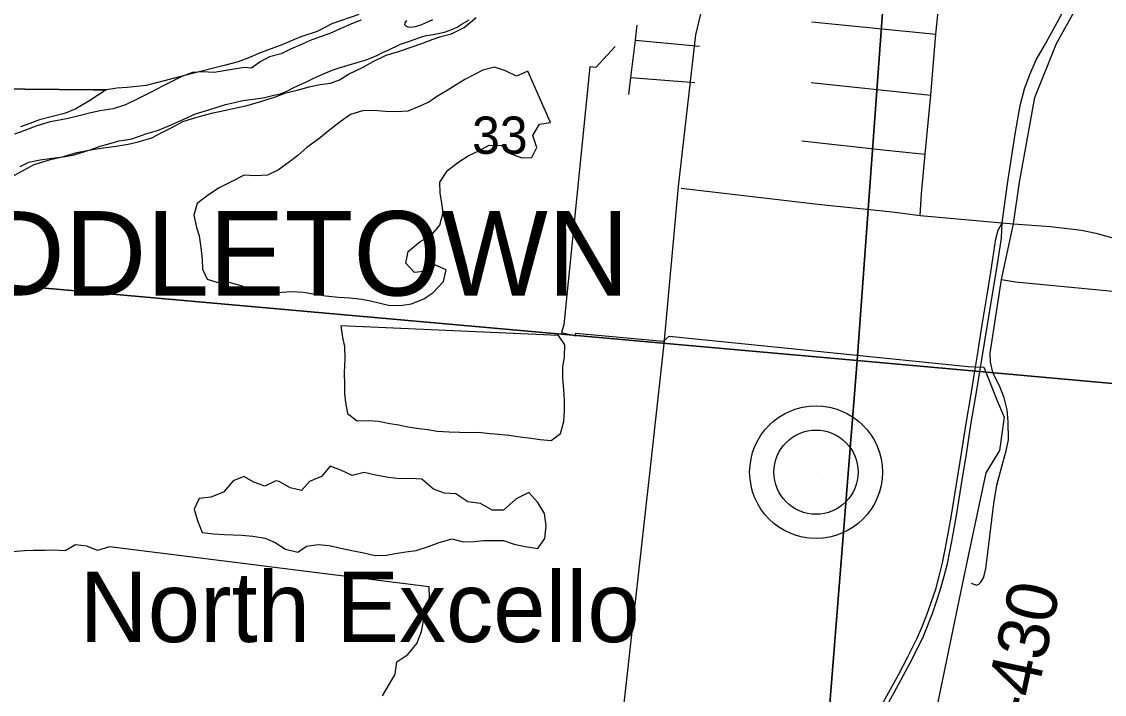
# Model space of a CAD drawing. Extents: x 0 to 34, y 0 to 22.
# Drawn here: x 4.533 to 5.747, y 15.439 to 16.193 of the extents above; entities that cross this region are included whole.
import ezdxf

# ---------------------------------------------------------------- set-up
doc = ezdxf.new("R2010")
doc.units = 0
for name, color, linetype in [('GM_X_City_Street', 7, 'Continuous'), ('GM_X_Corporation', 7, 'Continuous'), ('GM_X_Corporation_Text', 7, 'Continuous'), ('GM_X_County_Road', 7, 'Continuous'), ('GM_X_Major_River', 7, 'Continuous'), ('GM_X_Minor_Lake', 7, 'Continuous'), ('GM_X_Rail_Line', 7, 'Continuous'), ('GM_X_Section_Text', 7, 'Continuous'), ('GM_X_State_Route', 7, 'Continuous'), ('GM_X_Township_Road_Text', 7, 'Continuous'), ('GM_X_Unincorporated', 7, 'Continuous'), ('GM_X_Unincorporated_Location', 7, 'Continuous'), ('GM_X_Unincorporated_Text', 7, 'Continuous')]:
    doc.layers.add(name, color=color, linetype=linetype)

msp = doc.modelspace()

# ---------------------------------------------------------------- linework, layer by layer
at = {"layer": 'GM_X_City_Street'}
for p, q in [((5.4189, 16.1929), (5.5578, 16.1793)), ((5.2208, 16.1726), (5.2929, 16.1656)), ((5.2157, 16.1306), (5.2876, 16.1251)), ((5.4181, 16.1248), (5.5521, 16.1109))]:
    msp.add_line(p, q, dxfattribs=at)
for points in [[(5.5402, 15.9759), (5.5418, 16.0002), (5.546, 16.0446), (5.5521, 16.1109), (5.5578, 16.1793), (5.5645, 16.2444), (5.5717, 16.3105), (5.5762, 16.3524), (5.5785, 16.3733)], [(5.5973, 15.5632), (5.6032, 15.5612), (5.606, 15.5621), (5.6079, 15.5641), (5.6112, 15.5693), (5.6137, 15.5793), (5.623, 15.6529), (5.6262, 15.6733), (5.633, 15.6984), (5.6367, 15.7118), (5.6391, 15.7242), (5.6388, 15.7447), (5.6378, 15.7578), (5.6345, 15.7712), (5.6298, 15.7827), (5.6217, 15.7997), (5.6191, 15.8114), (5.6187, 15.8214), (5.6313, 15.904), (5.6449, 15.9664), (5.6515, 16.0131), (5.6577, 16.0459), (5.6687, 16.1082), (5.6931, 16.1687), (5.7153, 16.2082)], [(5.2134, 16.1115), (5.2157, 16.1306), (5.2208, 16.1726), (5.2228, 16.1891)], [(5.4076, 16.0595), (5.5022, 16.0491), (5.546, 16.0446)], [(5.6313, 15.904), (5.647, 15.9012), (5.7952, 15.887)]]:
    msp.add_lwpolyline(points, dxfattribs=at)
at = {"layer": 'GM_X_Corporation'}
for points in [[(5.5455, 16.8552), (5.4696, 15.8133), (4.4791, 15.9012)], [(4.9106, 16.2014), (4.8804, 16.1907), (4.864, 16.1823), (4.8456, 16.1763), (4.8242, 16.1673), (4.7994, 16.158), (4.788, 16.1529), (4.7754, 16.1483), (4.7613, 16.1444), (4.7197, 16.1339), (4.6721, 16.1217), (4.6509, 16.1195), (4.6395, 16.1186), (4.6326, 16.1176), (4.6273, 16.1166), (4.6133, 16.1169), (4.1502, 16.1212)], [(4.5308, 16.0308), (4.5407, 16.0355), (4.5533, 16.0383), (4.5643, 16.0396), (4.573, 16.0409), (4.5814, 16.0418), (4.5913, 16.0439), (4.6104, 16.0499), (4.6207, 16.0535), (4.6329, 16.057), (4.6416, 16.0595), (4.6473, 16.0601), (4.6561, 16.0618), (4.6637, 16.0643), (4.6717, 16.0672), (4.6851, 16.071), (4.6977, 16.0764), (4.7145, 16.084), (4.7275, 16.0898), (4.7424, 16.0944), (4.7611, 16.1001), (4.7713, 16.1025), (4.7805, 16.1046), (4.8036, 16.1079), (4.8155, 16.1107), (4.8227, 16.1124), (4.8307, 16.1156), (4.8384, 16.1196), (4.8514, 16.1254), (4.8617, 16.1305), (4.8736, 16.1359), (4.882, 16.1392), (4.8888, 16.1413), (4.9087, 16.1473), (4.9178, 16.1501), (4.93, 16.1548), (4.9381, 16.1588), (4.943, 16.1609), (4.9576, 16.1678), (4.9687, 16.1717), (4.9809, 16.176), (4.9866, 16.1778), (4.9942, 16.1788), (5.0067, 16.1815), (5.0151, 16.1844), (5.0209, 16.1869), (5.0266, 16.1906), (5.0343, 16.1953)], [(4.9934, 16.1951), (4.9808, 16.1897), (4.9739, 16.1875), (4.9686, 16.1865), (4.9659, 16.187), (4.9637, 16.1881), (4.9622, 16.1897), (4.9626, 16.192), (4.9646, 16.1946)], [(5.1983, 16.1652), (5.1765, 16.1419), (5.1697, 16.1427), (5.1405, 15.853), (5.1381, 15.8447), (5.1538, 15.8409), (5.1541, 15.8438), (5.2522, 15.835), (5.2587, 15.8404), (5.4471, 15.8212), (5.594, 15.8064), (5.6117, 15.8058), (5.6271, 15.7673), (5.6343, 15.7496), (5.6292, 15.712), (5.6139, 15.6872), (5.5936, 15.592), (5.5853, 15.5528), (5.5629, 15.4444), (5.5342, 15.3055)], [(4.1502, 16.1212), (4.6133, 16.1169), (4.6273, 16.1166), (4.6081, 16.1041), (4.5935, 16.0954), (4.5817, 16.0907), (4.5527, 16.083), (4.5417, 16.0791), (4.5314, 16.0751)]]:
    msp.add_lwpolyline(points, dxfattribs=at)
for points in [[(5.5455, 16.8552), (6.5907, 16.7563), (6.5598, 16.3771), (6.5104, 15.9318), (6.4956, 15.7207), (5.4696, 15.8133)], [(4.4791, 15.9012), (5.4696, 15.8133), (5.3881, 14.7897), (4.6238, 14.8425), (4.6032, 14.8565), (4.5856, 14.8637), (4.5735, 14.8663), (4.5679, 14.8668), (4.5637, 14.865), (4.5556, 14.8606), (4.5464, 14.8574), (4.5354, 14.8542), (4.5274, 14.851), (4.4054, 15.0286)], [(5.4696, 15.8133), (6.4956, 15.7207), (6.423, 14.72), (5.3881, 14.7897)]]:
    msp.add_lwpolyline(points, close=True, dxfattribs=at)
at = {"layer": 'GM_X_County_Road'}
for points in [[(5.2723, 16.0064), (5.429, 15.9882), (5.451, 15.9859)], [(5.451, 15.9859), (5.4731, 15.9837), (5.5054, 15.9802), (5.5203, 15.9784)], [(5.5203, 15.9784), (5.5402, 15.9759), (5.632, 15.9677)], [(5.632, 15.9677), (5.6449, 15.9664), (5.6862, 15.9633), (5.7212, 15.9592), (5.7372, 15.9561), (5.7521, 15.9519), (5.7668, 15.9473), (5.7841, 15.9435), (5.802, 15.9412), (5.8282, 15.9389), (5.9421, 15.9278), (6.0649, 15.9174), (6.1114, 15.9127), (6.1845, 15.9048), (6.2738, 15.8961), (6.3586, 15.8898), (6.3752, 15.8883), (6.4414, 15.8823), (6.496, 15.8771), (6.518, 15.8755)]]:
    msp.add_lwpolyline(points, dxfattribs=at)
at = {"layer": 'GM_X_Major_River'}
for points in [[(4.5203, 16.0188), (4.5341, 16.0264), (4.5468, 16.0329), (4.5648, 16.0385), (4.5794, 16.0419), (4.5943, 16.0465), (4.6122, 16.0498), (4.6244, 16.0517), (4.6386, 16.0536), (4.6519, 16.0559), (4.6634, 16.0583), (4.6787, 16.0628), (4.6899, 16.0689), (4.7026, 16.0754), (4.7134, 16.0812), (4.7268, 16.0854), (4.7371, 16.0882), (4.7474, 16.0909), (4.7596, 16.0936), (4.7696, 16.0957), (4.7856, 16.099), (4.7994, 16.1032), (4.8174, 16.1088), (4.8278, 16.1131), (4.8415, 16.1165), (4.8565, 16.1203), (4.8675, 16.1226), (4.879, 16.1242), (4.8889, 16.1281), (4.899, 16.1343), (4.9155, 16.1422), (4.9267, 16.1484), (4.9413, 16.1556), (4.954, 16.1594), (4.9728, 16.1657), (4.9831, 16.1693), (4.9931, 16.1732), (5.0027, 16.1767), (5.0145, 16.1794), (5.0288, 16.1866), (5.0424, 16.1977)], [(4.9132, 16.195), (4.9024, 16.1908), (4.889, 16.1847), (4.8782, 16.18), (4.8675, 16.1762), (4.856, 16.1719), (4.8464, 16.1676), (4.8341, 16.1622), (4.8237, 16.1572), (4.8107, 16.1538), (4.7999, 16.148), (4.7902, 16.141), (4.7823, 16.1417)], [(4.7823, 16.1417), (4.7483, 16.1361), (4.7354, 16.1368), (4.724, 16.136), (4.7121, 16.1317), (4.7025, 16.1267), (4.6913, 16.1213), (4.677, 16.1137), (4.662, 16.1061), (4.6489, 16.1), (4.6352, 16.0955), (4.6207, 16.0932), (4.6103, 16.0908), (4.597, 16.0874), (4.5847, 16.0847), (4.5752, 16.0827), (4.5645, 16.0807), (4.5496, 16.0765), (4.535, 16.0708), (4.5246, 16.0669)]]:
    msp.add_lwpolyline(points, dxfattribs=at)
at = {"layer": 'GM_X_Minor_Lake'}
for points in [[(5.1003, 16.1376), (5.0876, 16.1319), (5.0753, 16.1379), (5.0629, 16.1421), (5.0499, 16.1386), (5.0395, 16.1336), (5.0294, 16.1282), (5.0198, 16.1223), (5.0097, 16.1158), (4.9989, 16.1096), (4.9893, 16.103), (4.9766, 16.0973), (4.9658, 16.0927), (4.9533, 16.0919), (4.9407, 16.0926), (4.9271, 16.0937), (4.9149, 16.0933), (4.9015, 16.0891), (4.8899, 16.081), (4.8763, 16.0704), (4.8658, 16.0616), (4.8523, 16.0521), (4.8422, 16.0432), (4.8313, 16.0348), (4.8205, 16.0271), (4.8081, 16.021), (4.7948, 16.0202), (4.7823, 16.0209), (4.7669, 16.013), (4.7542, 16.0069), (4.7422, 15.9988), (4.7294, 15.9893), (4.7256, 15.9761), (4.7287, 15.9624), (4.7315, 15.9528), (4.7334, 15.9398), (4.7349, 15.9265), (4.7354, 15.9155), (4.7407, 15.9043), (4.7539, 15.9002), (4.765, 15.901), (4.7785, 15.8973), (4.792, 15.892), (4.8045, 15.8901), (4.8144, 15.8887), (4.8243, 15.8896), (4.8357, 15.8904), (4.8486, 15.8897), (4.8595, 15.8879), (4.8735, 15.8856), (4.8879, 15.8841), (4.9008, 15.8833), (4.914, 15.8818), (4.9239, 15.8801), (4.9348, 15.8775), (4.9454, 15.8749), (4.9598, 15.8753), (4.9697, 15.8766), (4.9835, 15.8823), (4.9936, 15.8892), (5.0057, 15.9018), (5.0087, 15.915), (4.9967, 15.9202), (4.9863, 15.9133), (4.9733, 15.9118), (4.9634, 15.9223), (4.966, 15.9355), (4.9796, 15.9465), (4.9916, 15.953), (5.0014, 15.9649), (5.0052, 15.9792), (5.0033, 15.9918), (5.002, 16.0013), (5.0016, 16.0131), (5.0103, 16.0262), (5.0227, 16.0361), (5.0335, 16.0426), (5.0462, 16.0487), (5.057, 16.0545), (5.0711, 16.0541), (5.0822, 16.0444), (5.0935, 16.0406), (5.1049, 16.0407), (5.1105, 16.052), (5.1059, 16.0654), (5.1135, 16.0781), (5.1257, 16.08)], [(5.1257, 16.08), (5.1003, 16.1376)], [(4.8904, 15.8521), (4.8923, 15.8388), (4.8947, 15.8288), (4.8951, 15.8148), (4.8943, 15.7996), (4.8947, 15.7859), (4.8948, 15.7757), (4.8957, 15.7662), (4.898, 15.7536), (4.9087, 15.7453), (4.922, 15.7457), (4.9327, 15.7451), (4.9455, 15.7424), (4.9557, 15.741), (4.9655, 15.7389), (4.978, 15.737), (4.9882, 15.7356), (4.9984, 15.7338), (5.0121, 15.7331), (5.0352, 15.7324), (5.0447, 15.7326), (5.058, 15.7311), (5.0678, 15.7304), (5.0788, 15.7294), (5.0917, 15.7275), (5.1038, 15.726), (5.114, 15.7246), (5.1265, 15.7235), (5.1369, 15.7312), (5.1407, 15.7448), (5.1414, 15.7565), (5.1414, 15.7687), (5.1406, 15.7805), (5.1394, 15.793), (5.1394, 15.8056), (5.1412, 15.8173), (5.1416, 15.8306), (5.1347, 15.841)], [(5.1347, 15.841), (4.8904, 15.8521)], [(5.0871, 15.6578), (5.073, 15.6453), (5.0601, 15.6452), (5.0471, 15.6528), (5.0331, 15.6547), (5.0196, 15.6634), (5.0068, 15.6645), (4.9943, 15.669), (4.9814, 15.68), (4.9685, 15.6807), (4.9567, 15.6803), (4.9438, 15.6818), (4.9295, 15.6844), (4.9166, 15.6874), (4.9033, 15.684), (4.8905, 15.69), (4.8785, 15.6945), (4.8687, 15.683), (4.8552, 15.6773), (4.8466, 15.6673), (4.8338, 15.6703), (4.8214, 15.6774), (4.8177, 15.6783)], [(4.8177, 15.6783), (4.8053, 15.6722), (4.7929, 15.6767), (4.7817, 15.6831), (4.7698, 15.6781), (4.7588, 15.6655), (4.7446, 15.6598), (4.7317, 15.6582), (4.726, 15.6462), (4.7298, 15.6336), (4.7352, 15.6202), (4.7477, 15.6187), (4.7602, 15.618), (4.7697, 15.6177), (4.7795, 15.6171), (4.792, 15.616), (4.8056, 15.6137), (4.8169, 15.6089), (4.8285, 15.6017), (4.8424, 15.5983), (4.8521, 15.6049), (4.865, 15.6068), (4.8775, 15.6057), (4.8904, 15.6027), (4.9028, 15.6001), (4.9164, 15.5975), (4.9289, 15.5945), (4.9414, 15.5949), (4.954, 15.5972), (4.9635, 15.5985), (4.975, 15.6001), (4.9888, 15.6046), (5.0007, 15.6089), (5.0152, 15.613), (5.0276, 15.6097), (5.0402, 15.6101), (5.0505, 15.6113), (5.0634, 15.6114), (5.0729, 15.6111), (5.0849, 15.607), (5.0974, 15.6044), (5.1113, 15.6021), (5.1193, 15.6136), (5.1208, 15.6277), (5.1189, 15.6414), (5.1113, 15.6537), (5.1013, 15.665)], [(5.1013, 15.665), (5.0871, 15.6578)], [(4.6311, 15.604), (4.6177, 15.6002), (4.6057, 15.605), (4.5928, 15.6065), (4.5812, 15.5996), (4.5679, 15.6004), (4.5584, 15.6002), (4.5455, 15.6002), (4.5356, 15.5997), (4.5223, 15.5985)], [(4.9894, 15.5591), (4.6311, 15.604)], [(4.9371, 15.4371), (4.9446, 15.4498), (4.9514, 15.4614), (4.9533, 15.475), (4.9657, 15.4834), (4.9759, 15.4956), (4.9808, 15.5092), (4.9834, 15.5213), (4.9864, 15.5333), (4.9898, 15.5469), (4.9894, 15.5591)]]:
    msp.add_lwpolyline(points, dxfattribs=at)
at = {"layer": 'GM_X_Rail_Line'}
msp.add_lwpolyline([(5.1979, 15.3351), (5.2386, 15.6999), (5.2531, 15.832), (5.2693, 16.0082), (5.2885, 16.1784), (5.3068, 16.2558), (5.3233, 16.355), (5.3206, 16.4015), (5.3247, 16.4679), (5.3834, 16.6331), (5.4012, 16.6697), (5.7083, 17.104), (6.1376, 17.7065), (6.2013, 17.8008), (6.2236, 17.8232), (6.2638, 17.8397), (6.3371, 17.8588)], dxfattribs=at)
at = {"layer": 'GM_X_State_Route'}
msp.add_line((5.5734, 15.5988), (5.5753, 15.6082), dxfattribs=at)
for points in [[(5.632, 15.9677), (5.6381, 16.0111), (5.6412, 16.0307), (5.6468, 16.067), (5.6522, 16.099), (5.6574, 16.1177), (5.6633, 16.1339), (5.6704, 16.1502), (5.6795, 16.1666), (5.6896, 16.1848), (5.7014, 16.206)], [(5.568, 15.5994), (5.5698, 15.6089), (5.5748, 15.6374), (5.5809, 15.6746), (5.587, 15.7114), (5.5916, 15.7404), (5.5978, 15.7777), (5.6008, 15.7967), (5.604, 15.8167), (5.6099, 15.8533), (5.6153, 15.8868), (5.6193, 15.9122), (5.6252, 15.9495), (5.6278, 15.9592), (5.632, 15.9677)], [(5.6083, 15.8074), (5.6095, 15.8144), (5.6153, 15.8508), (5.6215, 15.8876), (5.6258, 15.914), (5.6314, 15.9504), (5.6318, 15.9592), (5.632, 15.9677)], [(5.5753, 15.6082), (5.5804, 15.6371), (5.5866, 15.6744), (5.5924, 15.7108), (5.5972, 15.7408), (5.6042, 15.7821), (5.6068, 15.7984), (5.6083, 15.8074)], [(5.3942, 15.0951), (5.3949, 15.1036), (5.395, 15.1055), (5.3963, 15.1234), (5.3983, 15.1528), (5.4018, 15.1866), (5.4052, 15.2082), (5.408, 15.2234), (5.4127, 15.2406), (5.4174, 15.2571), (5.4255, 15.2787), (5.4366, 15.3038), (5.4465, 15.3236), (5.4699, 15.3663), (5.4896, 15.4021), (5.5109, 15.4407), (5.5311, 15.4782), (5.5438, 15.504), (5.554, 15.5294), (5.5587, 15.5428), (5.5631, 15.5565), (5.5672, 15.5712), (5.5708, 15.5855), (5.5734, 15.5988)], [(5.4419, 15.3262), (5.4519, 15.3448), (5.4658, 15.3698), (5.485, 15.4047), (5.4942, 15.4214), (5.5051, 15.4413), (5.5161, 15.4612), (5.5262, 15.4806), (5.5367, 15.5018), (5.5427, 15.5155), (5.548, 15.529), (5.5531, 15.543), (5.5576, 15.5566), (5.5616, 15.5713), (5.5653, 15.5861), (5.568, 15.5994)]]:
    msp.add_lwpolyline(points, dxfattribs=at)
at = {"layer": 'GM_X_Unincorporated'}
for radius in [0.0744, 0.0472]:
    msp.add_circle((5.4234, 15.6879), radius, dxfattribs=at)
at = {"layer": 'GM_X_Unincorporated_Location'}
msp.add_line((5.4234, 15.6879), (5.4234, 15.6879), dxfattribs=at)

# ---------------------------------------------------------------- texts
at = {"layer": 'GM_X_Corporation_Text'}
msp.add_text('MIDDLETOWN', height=0.0947, rotation=0, dxfattribs=at).set_placement((4.3488, 15.886))
at = {"layer": 'GM_X_Section_Text'}
msp.add_text('33', height=0.04186, rotation=0, dxfattribs=at).set_placement((5.0377, 16.0449))
at = {"layer": 'GM_X_Township_Road_Text'}
msp.add_text('T-430', height=0.05682, rotation=77.8661, dxfattribs=at).set_placement((5.6558, 15.3633))
at = {"layer": 'GM_X_Unincorporated_Text'}
msp.add_text('North Excello', height=0.078977, rotation=0, dxfattribs=at).set_placement((4.5977, 15.4973))

doc.saveas('drawing.dxf')
